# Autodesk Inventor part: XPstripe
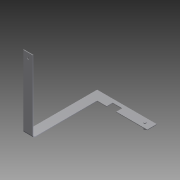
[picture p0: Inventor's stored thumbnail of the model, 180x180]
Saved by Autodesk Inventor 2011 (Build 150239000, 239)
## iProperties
Created: 2014-11
Part Number: XPstripe
Document SubType Name: Modeling
Designer: Evgeny
Density: 1 g/cm^3
Author: Evgeny
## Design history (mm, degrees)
sketch "Эскиз1"
  geometry: L1 (17, 32)-(-8, 32); L2 (17, 28)-(17, 32); L3 (-4, 28)-(-4, 1); L4 (-4, 1)-(-8, 1); L5 (-8, 32)-(-8, 1); L6 (0, 28)-(0, 30.5); L7 (0, 30.5)-(4, 30.5); L8 (4, 30.5)-(4, 28); L9 (-4, 28)-(0, 28); L10 (4, 28)-(17, 28); C1 r 0.5 at (14, 30); 1 further point
  constraints: 20 end point, 3 parallel, 1 centre point, 1 collinear, 1 horizontal, 1 perpendicular
  dimensions: "d0" = 31 distance between parallel lines of L4 L1; "d1" = 25 distance between parallel lines of L5 L2; "d2" = 4 distance between parallel lines of L3 L5; "d3" = 1 diameter of C1; "d4" = 3 distance from line of L2 C1.centre; "d5" = 4 distance between parallel lines of L1 L10; "d6" = 2 distance from line of L1 C1.centre; "d7" = 13 distance between parallel lines of L8 L2; "d8" = 4 distance between parallel lines of L6 L8; "d9" = 1.5 distance between parallel lines of L7 L1
extrude "Выдавливание1" new body sketch "Эскиз1" distance "d10" = 0.25; taper "d11" = 0 deg
sketch "Эскиз2"
  geometry: L1 (-4, 28)-(-4, 1) reference; L2 (-8, 1)-(-4, 1); L3 (-4, 1)-(-4, 1.25); L4 (-4, 1.25)-(-8, 1.25); L5 (-8, 1.25)-(-8, 1); 1 further point
  constraints: 8 end point, 2 parallel, 1 horizontal, 1 perpendicular, 1 point on line
  dimensions: "d12" = 0.25 distance between parallel lines of L4 L2
extrude "Выдавливание2" join sketch "Эскиз2" distance "d13" = 30; taper "d14" = 0 deg
fillet "Сопряжение1" dims "d15" = 0.75
fillet "Сопряжение2" dims "d16" = 1
hole "Отверстие1" diameter "d19" = 1; stored, may be unused: countersink angle "d23" = 90 deg, drill point angle "d25" = 118 deg; dims "d17" = 2, "d18" = 2, "d20" = 6, "d21" = 4, "d22" = 2, "d24" = 1
extrude "Выдавливание3" join sketch "Эскиз1" distance "d26" = 2; taper "d28" = 0 deg; dims "d27" = 0.5, "d29" = 0
node "Твердое тело1"
